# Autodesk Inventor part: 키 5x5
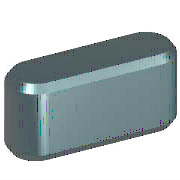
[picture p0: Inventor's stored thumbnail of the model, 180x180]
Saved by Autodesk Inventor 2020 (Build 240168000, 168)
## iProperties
IsCustomPart: 1
Created: 2012-02
Part Number: 키 5x5
Material: 강철, 연강
Description: 키 및 해당 키홈
Document SubType Name: Modeling
Standard: KS B 1311
Designer: mduedu
Standards Organization: KS
Language: ko-KR
Size Designation: 5 x 5 x 12
Categories: <MemberInstance><Categories><Category DisplayName="샤프트 부품" InternalName="7f7aeb1f-a693-4053-b835-cee3144e0d98" Mnemonic="SHFT"><Category DisplayName="키" Interna
Density: 1 g/cm^3
Appearance: 노란색
Author: mduedu
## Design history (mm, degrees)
workplane "Work Plane1"
workplane "Work Plane2"
sketch "스케치1"
  geometry: L1 (2.5, 2.5)-(9.5, 2.5); L2 (9.5, -2.5)-(2.5, -2.5); L3 (0, 9.4)-(0, -7.4) reference; L4 (-5, 0)-(30, 0) reference; L5 (12, 0)-(12, 7); A1 r 2.5 centre (2.5, 0) between (2.5, 2.5) and (2.5, -2.5); A2 r 2.5 centre (9.5, 0) between (9.5, -2.5) and (9.5, 2.5)
  constraints: 6 end point, 5 point on circle, 4 tangent, 3 point on line, 2 centre point, 1 horizontal, 1 parallel, 1 perpendicular
  dimensions: "d0" = 2.5 radius of A1 (= 0.5 x PB); "d13" = 2.5 radius of A2 (= 0.5 x PB); "d14" = 12 distance between parallel lines of L5 L3 (= NLG)
extrude "본체1" new body sketch "스케치1" taper "d3" = 0 deg; stored distance "d4" = 10
workplane "Work Plane3"
body "Solid1"
chamfer "모따기1" distance "d8" = 0.4 (= PHH); stored, may be unused: second distance "d9" = 0.4 (= PHH), angle "d15" = 45 deg
other parameters: "d1" = -3 (= -PNT), "d2" = 2 (= PH - PNT), "NLG" = 12 [user parameter; used in 3 equation terms], "PB" = 5 [user parameter; used in 2 equation terms], "PNT" = 3 [user parameter; used in 2 equation terms], "PH" = 5 [user parameter; used in 1 equation term], "PHH" = 0.4 [user parameter; used in 2 equation terms], "d10" = 0, "d16" = 0, "d17" = 0, "d18" = 0, "WDMIN" = 12 [user parameter], "PLB2" = 12 (= NLG) [user parameter], "WDMAX" = 17 [user parameter], "PLB1" = 12 (= NLG) [user parameter], "RR" = 0.16 [user parameter], "PUEB" = 2.3 [user parameter]
